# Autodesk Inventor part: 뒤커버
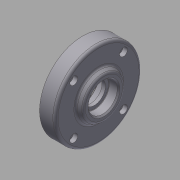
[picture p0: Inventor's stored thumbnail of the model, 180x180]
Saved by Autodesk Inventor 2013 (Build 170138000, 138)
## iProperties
Company: 한국ATC센터
Created: 2015-12
Part Number: 뒤커버
Document SubType Name: Modeling
Designer: mdu
Density: 2.71 g/cm^3
Mass: 97.9591 g
Surface Area: 115.525 cm^2
Volume: 36.1473 cm^3
Material: 알루미늄-6061
Author: mdu
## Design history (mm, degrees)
sketch "스케치1"
  geometry: L1 (-10.5, 0)-(10.5, 0); L2 (10.5, 0)-(10.5, 22.5); L3 (10.5, 22.5)-(5.5, 22.5); L4 (5.5, 22.5)-(5.5, 32.5); L5 (5.5, 32.5)-(-6.5, 32.5); L6 (-6.5, 32.5)-(-6.5, 17.5); L7 (-6.5, 17.5)-(-10.5, 15.191); L8 (-10.5, 15.191)-(-10.5, 0); 2 further points
  constraints: 16 end point, 3 parallel, 3 perpendicular, 1 coincident, 1 horizontal, 1 midpoint
  dimensions: "d0" = 21 distance of L1.start L1.end; "d1" = 65 diameter of L5 L1; "d2" = 45 diameter of L3 L1; "d3" = 35 diameter of L6.end L1; "d4" = 120 deg angle of L7 L6; "d5" = 12 distance of L4.end L5.end; "d6" = 5 distance of L2.end L3.end
revolve "회전1" sketch "스케치1" stored, may be unused: angle "d7" = 90 deg
sketch "스케치2"
  geometry: L1 (0, 0)-(32.5, 0); L2 (0, 0)-(18.738, 18.738); 1 further point
  constraints: 4 end point, 1 horizontal, 1 horizontal alignment, 1 other
  dimensions: "d8" = 45 deg angle of L1 L2; "d9" = 26.5 distance of L1.start L2.end
hole "구멍1" sketch "스케치2" at (18.738, 18.738) diameter "d10" = 3.4; stored, may be unused: countersink angle "d14" = 90 deg, drill point angle "d16" = 118 deg; dims "d11" = 6, "d12" = 6, "d13" = 3.3, "d15" = 8
fillet "모깎기1" dims "d20" = 2
hole "구멍2" diameter "d23" = 15; stored, may be unused: countersink angle "d27" = 90 deg, drill point angle "d29" = 0 deg; dims "d21" = 10, "d22" = 10, "d24" = 6, "d25" = 35, "d26" = 11, "d28" = 14
chamfer "모따기1" distance "d39" = 1; stored, may be unused: second distance "d40" = 2, angle "d41" = 45 deg
fillet "모깎기2" dims "d42" = 0.3
hole "구멍4" diameter "d46" = 17; stored, may be unused: countersink angle "d50" = 90 deg, drill point angle "d52" = 118 deg; dims "d44" = 10, "d45" = 10, "d47" = 6, "d48" = 22, "d49" = 7.3, "d51" = 8
chamfer "모따기2" distance "d53" = 1; stored, may be unused: second distance "d54" = 2, angle "d55" = 45 deg
fillet "모깎기3" dims "d56" = 0.3
node "솔리드1"
pattern_circular "원형 패턴1" dims angle "d18" = 360 deg
